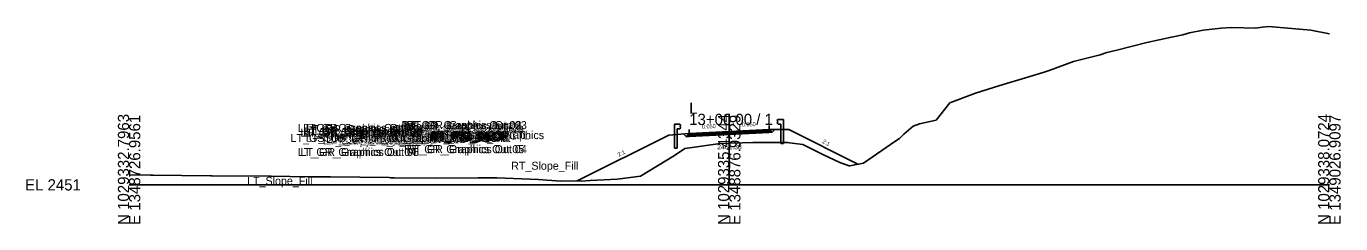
# Model space of a CAD drawing. Extents: x -26 to 1453, y -10 to 4527.
# Drawn here: x -25.7 to 302.8, y 2990.3 to 3039.6 of the extents above; entities that cross this region are included whole.
import ezdxf

# ---------------------------------------------------------------- set-up
doc = ezdxf.new("R2010")
doc.units = 0
for name, color, linetype in [('Default', 7, 'Continuous'), ('Exist Cross Section Cell', 7, 'Continuous'), ('Exist XS Center Line Elevation Label', 7, 'Continuous'), ('Exist XS Ground Line', 7, 'Continuous'), ('Prop CMT Guardrail Graphics', 7, 'Continuous'), ('Prop CMT Pvmt Course 1', 7, 'Continuous'), ('Prop CMT Pvmt Course 2', 7, 'Continuous'), ('Prop CMT Pvmt Course 3', 7, 'Continuous'), ('Prop CMT Pvmt Surface', 7, 'Continuous'), ('Prop CMT Pvmt Surface Overlay', 7, 'Continuous'), ('Prop CMT Pvmt Surface Shoulder', 7, 'Continuous'), ('Prop CMT Shld Paved Course 1', 7, 'Continuous'), ('Prop CMT Shld Paved Course 2', 7, 'Continuous'), ('Prop CMT Shld Paved Course 3', 7, 'Continuous'), ('Prop CMT Slope Grass', 7, 'Continuous'), ('Prop CMT Subgrade Earthwork', 7, 'Continuous'), ('Prop XS Earthwork Shape', 7, 'Continuous'), ('Prop XS EOT Tick Mark', 7, 'Continuous'), ('Prop XS SE Text', 7, 'Continuous'), ('Prop XS Side Slope Text', 7, 'Continuous')]:
    doc.layers.add(name, color=color, linetype=linetype)

msp = doc.modelspace()

# ---------------------------------------------------------------- linework, layer by layer
at = {"layer": 'Exist Cross Section Cell'}
for p, q in [((150, 3000), (150, 3017.74)), ((0, 3000), (150, 3000)), ((150, 3000), (300, 3000))]:
    msp.add_line(p, q, dxfattribs=at)
at = {"layer": 'Exist XS Ground Line'}
msp.add_lwpolyline([(0, 3002.46), (5.37, 3002.41), (6.05, 3002.4), (20.37, 3002.23), (20.79, 3002.23), (35.37, 3002.15), (35.54, 3002.14), (44.96, 3002.03), (50.28, 3001.97), (50.37, 3001.97), (65.02, 3001.8), (65.39, 3001.79), (66.34, 3001.79), (76.69, 3001.69), (87.24, 3001.77), (91.91, 3001.75), (102.31, 3001.37), (107.87, 3000.91), (112.49, 3000.97), (113.15, 3000.92), (115.25, 3001.09), (121.97, 3001.44), (127.8, 3002.17), (136.32, 3007.33), (138.88, 3009.04), (140.78, 3009.28), (147.72, 3010.3), (150, 3010.38), (153.23, 3010.5), (155.93, 3010.59), (163.77, 3010.57), (164.61, 3010.57), (165.1, 3010.51), (168.4, 3010.06), (173.38, 3007.57), (177.68, 3005.55), (180.02, 3004.77), (180.07, 3004.76), (180.14, 3004.78), (183.53, 3005.45), (191.36, 3010.8), (192.54, 3011.58), (193.67, 3012.66), (195.95, 3014.63), (197.52, 3015.25), (201.69, 3016.18), (205.15, 3020.46), (205.17, 3020.48), (205.18, 3020.48), (211.54, 3022.89), (216.02, 3024.28), (218.5, 3025.07), (224.08, 3026.74), (228.71, 3028.09), (229.93, 3028.54), (236.06, 3030.81), (242.71, 3032.49), (244.38, 3033), (246.9, 3033.65), (254.41, 3035.5), (260.51, 3036.89), (263.38, 3037.47), (265.03, 3037.9), (268.44, 3038.58), (269.95, 3038.74), (272.92, 3039.14), (275.58, 3039.26), (281.6, 3039.14), (283.19, 3039.39), (284.87, 3039.56), (295.35, 3038.63), (300, 3037.65)], dxfattribs=at)
at = {"layer": 'Prop CMT Guardrail Graphics'}
for points in [[(163.54, 3016.31), (162.21, 3016.31), (161.94, 3016.02)], [(161.94, 3016.02), (162.21, 3015.73)], [(163.54, 3010.31), (163.54, 3016.31)], [(136.3, 3009.17), (136.3, 3015.17)], [(136.3, 3015.17), (137.63, 3015.17), (137.9, 3014.87)], [(137.9, 3014.29), (137.63, 3014), (136.96, 3014)], [(136.96, 3014), (136.96, 3009.17)], [(137.9, 3014.87), (137.63, 3014.58)], [(137.63, 3014.58), (137.9, 3014.29)], [(162.21, 3015.73), (161.94, 3015.44)], [(161.94, 3015.44), (162.21, 3015.15), (162.88, 3015.15)], [(162.88, 3015.15), (162.88, 3010.31)], [(162.88, 3010.31), (163.54, 3010.31)], [(136.96, 3009.17), (136.3, 3009.17)]]:
    msp.add_lwpolyline(points, dxfattribs=at)
at = {"layer": 'Prop CMT Pvmt Course 1'}
for points in [[(150, 3013.33), (140, 3012.83)], [(140, 3012.58), (150, 3013.08)], [(140, 3012.83), (140, 3012.58)], [(150, 3013.33), (160, 3013.83)], [(160, 3013.58), (150, 3013.08)], [(150, 3013.21), (150, 3013.33)], [(150, 3013.21), (150, 3013.33)], [(150, 3013.08), (150, 3013.21), (150, 3013.21)], [(150, 3013.08), (150, 3013.21), (150, 3013.21)], [(160, 3013.83), (160, 3013.58)]]:
    msp.add_lwpolyline(points, dxfattribs=at)
at = {"layer": 'Prop CMT Pvmt Course 2'}
for points in [[(150, 3013.08), (140, 3012.58)], [(140, 3012.33), (150, 3012.83)], [(150, 3013.08), (160, 3013.58)], [(160, 3013.33), (150, 3012.83)], [(150, 3012.83), (150, 3013.08)], [(150, 3012.83), (150, 3013.08)], [(160, 3013.58), (160, 3013.33)], [(140, 3012.58), (140, 3012.33)]]:
    msp.add_lwpolyline(points, dxfattribs=at)
at = {"layer": 'Prop CMT Pvmt Course 3'}
for points in [[(150, 3012.83), (140, 3012.33)], [(150, 3012.83), (160, 3013.33)], [(160, 3013.08), (150, 3012.58)], [(150, 3012.58), (150, 3012.83)], [(150, 3012.58), (150, 3012.83)], [(160, 3013.33), (160, 3013.08)], [(140, 3012.08), (150, 3012.58)], [(140, 3012.33), (140, 3012.08)]]:
    msp.add_lwpolyline(points, dxfattribs=at)
at = {"layer": 'Prop CMT Pvmt Surface'}
for points in [[(150, 3013.33), (140, 3012.83)], [(150, 3013.33), (160, 3013.83)]]:
    msp.add_lwpolyline(points, dxfattribs=at)
at = {"layer": 'Prop CMT Pvmt Surface Overlay'}
for points in [[(150, 3013.33), (140, 3012.83)], [(150, 3013.33), (160, 3013.83)]]:
    msp.add_lwpolyline(points, dxfattribs=at)
at = {"layer": 'Prop CMT Pvmt Surface Shoulder'}
for points in [[(140, 3012.83), (140, 3012.83)], [(160, 3013.83), (160, 3013.83)]]:
    msp.add_lwpolyline(points, dxfattribs=at)
at = {"layer": 'Prop CMT Shld Paved Course 1'}
for points in [[(140, 3012.83), (140, 3012.83), (139.74, 3012.57)], [(140, 3012.58), (140, 3012.83)], [(160, 3013.83), (160, 3013.83), (160.24, 3013.6)], [(160, 3013.58), (160, 3013.83)], [(160.24, 3013.6), (160, 3013.58)], [(139.74, 3012.57), (140, 3012.58)]]:
    msp.add_lwpolyline(points, dxfattribs=at)
at = {"layer": 'Prop CMT Shld Paved Course 2'}
for points in [[(160, 3013.58), (160.24, 3013.6), (160.48, 3013.36)], [(160, 3013.33), (160, 3013.58)], [(160.48, 3013.36), (160, 3013.33)], [(140, 3012.58), (139.74, 3012.57), (139.47, 3012.31)], [(139.47, 3012.31), (140, 3012.33)], [(140, 3012.33), (140, 3012.58)]]:
    msp.add_lwpolyline(points, dxfattribs=at)
at = {"layer": 'Prop CMT Shld Paved Course 3'}
for points in [[(160, 3013.33), (160.48, 3013.36)], [(160, 3013.08), (160, 3013.33)], [(160.72, 3013.12), (160, 3013.08)], [(160.48, 3013.36), (160.48, 3013.36)], [(160.48, 3013.36), (160.72, 3013.12)], [(139.47, 3012.31), (139.21, 3012.04)], [(139.21, 3012.04), (140, 3012.08)], [(140, 3012.33), (139.47, 3012.31)], [(139.47, 3012.31), (139.47, 3012.31)], [(140, 3012.08), (140, 3012.33)]]:
    msp.add_lwpolyline(points, dxfattribs=at)
at = {"layer": 'Prop CMT Slope Grass'}
for points in [[(137.9, 3012.67), (134.9, 3012.43)], [(140, 3012.83), (137.9, 3012.67)], [(160, 3013.83), (161.94, 3013.81)], [(161.94, 3013.81), (164.94, 3013.78)], [(164.94, 3013.78), (182.16, 3005.18)], [(134.9, 3012.43), (111.98, 3000.97)]]:
    msp.add_lwpolyline(points, dxfattribs=at)
at = {"layer": 'Prop CMT Subgrade Earthwork'}
for points in [[(139.21, 3012.04), (138.54, 3012.72)], [(150, 3012.58), (160, 3013.08)], [(160, 3013.08), (160.72, 3013.12)], [(160.72, 3013.12), (161.42, 3013.82)], [(140, 3012.08), (139.21, 3012.04)], [(150, 3012.58), (140, 3012.08)]]:
    msp.add_lwpolyline(points, dxfattribs=at)
at = {"layer": 'Prop XS Earthwork Shape'}
msp.add_lwpolyline([(161.42, 3013.82), (161.94, 3013.81), (164.94, 3013.78), (182.16, 3005.18), (180.14, 3004.78), (180.07, 3004.76), (180.02, 3004.77), (177.68, 3005.55), (173.38, 3007.57), (168.4, 3010.06), (165.1, 3010.51), (164.61, 3010.57), (163.77, 3010.57), (155.93, 3010.59), (153.23, 3010.5), (150, 3010.38), (147.72, 3010.3), (140.78, 3009.28), (138.88, 3009.04), (136.32, 3007.33), (127.8, 3002.17), (121.97, 3001.44), (115.25, 3001.09), (113.15, 3000.92), (112.49, 3000.97), (111.98, 3000.97), (134.9, 3012.43), (137.9, 3012.67), (138.54, 3012.72), (139.21, 3012.04), (140, 3012.08), (150, 3012.58), (160, 3013.08), (160.72, 3013.12)], close=True, dxfattribs=at)
msp.add_lwpolyline([(161.42, 3013.82), (161.94, 3013.81), (164.94, 3013.78), (182.16, 3005.18), (180.14, 3004.78), (180.07, 3004.76), (180.02, 3004.77), (177.68, 3005.55), (173.38, 3007.57), (168.4, 3010.06), (165.1, 3010.51), (164.61, 3010.57), (163.77, 3010.57), (155.93, 3010.59), (153.23, 3010.5), (150, 3010.38), (147.72, 3010.3), (140.78, 3009.28), (138.88, 3009.04), (136.32, 3007.33), (127.8, 3002.17), (121.97, 3001.44), (115.25, 3001.09), (113.15, 3000.92), (112.49, 3000.97), (111.98, 3000.97), (134.9, 3012.43), (137.9, 3012.67), (138.54, 3012.72), (139.21, 3012.04), (140, 3012.08), (150, 3012.58), (160, 3013.08), (160.72, 3013.12)], close=True, dxfattribs=at)
at = {"layer": 'Prop XS EOT Tick Mark'}
for points in [[(140, 3012.83), (140, 3013.83)], [(160, 3013.83), (160, 3014.83)]]:
    msp.add_lwpolyline(points, dxfattribs=at)

# ---------------------------------------------------------------- texts
at = {"layer": 'Default'}
for s, height, p in [('RT_GR_Graphics Out 02', 2, (68.06, 3013.91)), ('RT_GR_Graphics Out 03', 2, (69.39, 3013.91)), ('LT_GS_OS_GR_Face_Graphics', 2, (40.36, 3010.7)), ('LT_GR_Graphics Out 03', 2, (42.19, 3013.2)), ('LT_GR_Graphics Out 06', 2, (42.81, 3012.03)), ('LT_GR_Graphics Out 02', 2, (43.53, 3013.2)), ('LT_GR_Graphics Out 09', 2, (43.53, 3012.61)), ('LT_GR_Graphics Out 07', 2, (43.53, 3012.03)), ('LT_GR_Graphics Out 08', 2, (43.8, 3012.32)), ('LT_Sub_Trench_Out_DLT', 2, (44.13, 3010.75)), ('LT_GR_Graphics Out 01', 2, (44.36, 3012.9)), ('LT_PV1_OEOT', 2, (55.74, 3010.86)), ('LT_PS1_OEOP', 2, (55.8, 3010.86)), ('LT_TM_OEOT', 2, (55.94, 3011.86)), ('RT_PV1_OEEOP_W', 2, (62.94, 3011.04)), ('LT_PV1_OEEOP_W', 2, (62.98, 3011.04)), ('RT_PV2_OEEOP', 2, (64.26, 3010.91)), ('RT_PV3_OEEOP', 2, (64.26, 3010.66)), ('LT_PV2_OEEOP', 2, (64.31, 3010.91)), ('LT_PV3_OEEOP', 2, (64.31, 3010.66)), ('RT_GS_OS_GR_Face_Graphics', 2, (64.35, 3011.41)), ('RT_Sub_Trench_Out_DLT', 2, (66.93, 3011.42)), ('PV1_PGL_W', 2, (67.58, 3011.04)), ('RT_GR_Graphics Out 08', 2, (67.79, 3013.03)), ('RT_GR_Graphics Out 09', 2, (68.06, 3013.32)), ('RT_GR_Graphics Out 07', 2, (68.06, 3012.74)), ('RT_GR_Graphics Out 01', 2, (68.36, 3013.61)), ('RT_GR_Graphics Out 06', 2, (68.68, 3012.74)), ('PV1_PGL', 2, (69.47, 3011.16)), ('RT_Sub_Trench_Out', 2, (69.89, 3010.74)), ('RT_PS3_Shelf_Out', 2, (71.42, 3010.98)), ('RT_Sub_OEOT', 2, (75.03, 3010.71)), ('RT_PV2_OEOT', 2, (75.13, 3011.21)), ('RT_PV3_OEOT', 2, (75.13, 3010.96)), ('RT_PS2_OEOP', 2, (75.43, 3011.22)), ('RT_PS3_OEOP', 2, (75.68, 3010.98)), ('RT_PV1_OEOT', 2, (75.69, 3011.46)), ('RT_PS1_OEOP', 2, (75.76, 3011.46)), ('RT_TM_OEOT', 2, (75.9, 3012.46)), ('RT_GS_OS_CTL', 2, (79.26, 3011.32)), ('LT_Sub_Trench_Out', 2, (48.43, 3010.09)), ('LT_GS_OS_CTL', 2, (49.27, 3010.46)), ('LT_PS3_Shelf_Out', 2, (50.47, 3010.35)), ('LT_PS3_OEOP', 2, (54.72, 3010.35)), ('LT_PS2_OEOP', 2, (54.98, 3010.61)), ('LT_Sub_OEOT', 2, (55.08, 3010.11)), ('LT_PV2_OEOT', 2, (55.17, 3010.61)), ('LT_PV3_OEOT', 2, (55.17, 3010.36)), ('RT_Sub_OEEOP', 2, (64.17, 3010.41)), ('LT_Sub_OEEOP', 2, (64.21, 3010.41)), ('RT_GR_Graphics Out 05', 2, (68.73, 3007.91)), ('RT_GR_Graphics Out 04', 2, (69.39, 3007.91)), ('LT_GR_Graphics Out 04', 2, (42.19, 3007.2)), ('LT_GR_Graphics Out 05', 2, (42.86, 3007.2)), ('RT_Slope_Fill', 2, (95.5, 3003.77)), ('-', 0.0001, (0, 3000)), ('-', 0.0001, (0, 3000)), ('-', 0.0001, (0, 3000)), ('-', 0.0001, (0, 3000)), ('LT_Slope_Fill', 2, (29.49, 2999.99))]:
    msp.add_text(s, height=height, dxfattribs=at).set_placement(p)
at = {"layer": 'Exist Cross Section Cell'}
for s, p in [('L', (140, 3017.74)), ('13+00.00 / 1', (140, 3014.94)), ('EL 2451', (-26, 2998.6))]:
    msp.add_text(s, height=2.8, dxfattribs=at).set_placement(p)
for s, p in [('N 1029332.7963', (0, 2990)), ('E 1348726.9561', (2.8, 2990)), ('N 1029335.4344', (150, 2990)), ('E 1348876.9329', (152.8, 2990)), ('N 1029338.0724', (300, 2990)), ('E 1349026.9097', (302.8, 2990))]:
    msp.add_text(s, height=2.8, rotation=90, dxfattribs=at).set_placement(p)
at = {"layer": 'Exist XS Center Line Elevation Label'}
msp.add_text('2461.38', height=1.23, dxfattribs=at).set_placement((146.99, 3008.87))
at = {"layer": 'Prop XS SE Text'}
for p in [(143.2, 3014), (153.2, 3014.5)]:
    msp.add_text('0.050', height=1, rotation=2.8624, dxfattribs=at).set_placement(p)
at = {"layer": 'Prop XS Side Slope Text'}
for rotation, p in [(333.4349, (173.17, 3010.51)), (26.5651, (122.4, 3007.01))]:
    msp.add_text('2:1', height=1, rotation=rotation, dxfattribs=at).set_placement(p)

doc.saveas('drawing.dxf')
